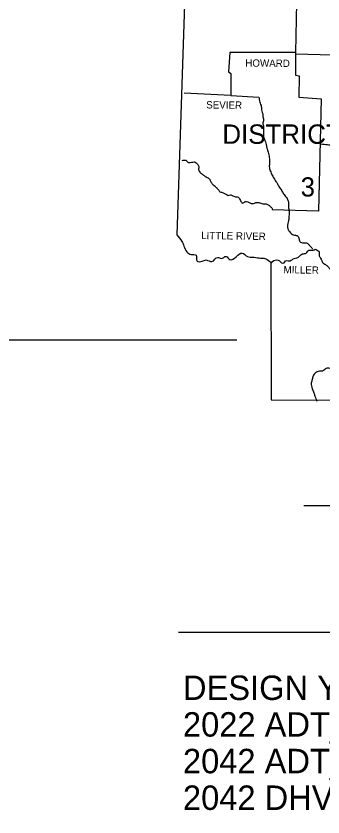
# Model space of a CAD drawing. Extents: x 1382482 to 1385815, y 1168351 to 1170484.
# Drawn here: x 1384992.8 to 1385181.4, y 1169422.5 to 1169914.2 of the extents above; entities that cross this region are included whole.
import ezdxf

# ---------------------------------------------------------------- set-up
doc = ezdxf.new("R2010")
doc.units = 0
for name, color, linetype in [('Default', 7, 'Continuous'), ('R_Dimension', 7, 'Continuous'), ('R_Draft', 7, 'Continuous')]:
    doc.layers.add(name, color=color, linetype=linetype)

msp = doc.modelspace()

# ---------------------------------------------------------------- linework, layer by layer
at = {"layer": 'Default'}
msp.add_line((1385169.72, 1169613.81), (1385528.6, 1169613.81), dxfattribs=at)
for points in [[(1385079.51, 1170236.59), (1385101.12, 1170063.06), (1385091.73, 1169779.8)], [(1385165.65, 1169943.09), (1385164.5, 1169891.73), (1385124.3, 1169891.83), (1385123.36, 1169879.93), (1385124.83, 1169878.88), (1385124.72, 1169865.52), (1385096.22, 1169866.77)], [(1385164.5, 1169891.73), (1385164.5, 1169877.84), (1385166.8, 1169877.42), (1385166.59, 1169864.47), (1385180.37, 1169863.43), (1385178.7, 1169794.42), (1385150.3, 1169795.15)], [(1385164.71, 1169890.99), (1385224.43, 1169889.43)], [(1385124.72, 1169865.52), (1385142.05, 1169864.47)], [(1385149.47, 1169762.99), (1385149.68, 1169678.52), (1385532.34, 1169677.9)]]:
    msp.add_lwpolyline(points, dxfattribs=at)
for points in [[(1385142.05, 1169864.47), (1385142.58, 1169861.34), (1385143.52, 1169858.63), (1385143.62, 1169856.54), (1385144.56, 1169853.41), (1385144.56, 1169852.26), (1385144.87, 1169849.96), (1385144.45, 1169848.71), (1385144.98, 1169846.2), (1385144.87, 1169844.32), (1385144.87, 1169842.76), (1385144.98, 1169840.15), (1385145.81, 1169837.85), (1385146.65, 1169834.4), (1385147.17, 1169832.63), (1385148, 1169829.92), (1385148.53, 1169826.57), (1385148.63, 1169824.07), (1385148.42, 1169821.77), (1385149.05, 1169819.16), (1385150.2, 1169816.55), (1385151.66, 1169814.04), (1385153.43, 1169811.23), (1385154.69, 1169809.03), (1385156.25, 1169806.63), (1385157.51, 1169804.65), (1385159.39, 1169802.14), (1385160.22, 1169800.05), (1385160.22, 1169797.13), (1385160.64, 1169794.42), (1385160.53, 1169791.39), (1385160.33, 1169788.67), (1385159.59, 1169784.91), (1385160.12, 1169783.14), (1385162.1, 1169780.53), (1385163.35, 1169779.8), (1385165.55, 1169779.38), (1385166.59, 1169777.92), (1385167.22, 1169775.73), (1385169.41, 1169775), (1385171.81, 1169774.79), (1385172.96, 1169773.53), (1385174.53, 1169771.86), (1385175.05, 1169771.03)], [(1385180.16, 1169835.66), (1385184.13, 1169835.34), (1385187.79, 1169834.93), (1385190.6, 1169834.61), (1385193.53, 1169833.57), (1385196.14, 1169832.63), (1385197.81, 1169831.9), (1385200.63, 1169832.11), (1385203.03, 1169831.59), (1385205.74, 1169830.65), (1385207.73, 1169828.87), (1385208.98, 1169827.51), (1385211.38, 1169826.99), (1385213.37, 1169827.3), (1385215.77, 1169827.1), (1385218.48, 1169826.26), (1385220.68, 1169826.37), (1385222.45, 1169826.78), (1385224.54, 1169827.3), (1385227.15, 1169827.51), (1385229.13, 1169827.1), (1385231.74, 1169826.99), (1385234.77, 1169827.3), (1385238.53, 1169826.26)], [(1385094.96, 1169825.53), (1385097.26, 1169825.63), (1385098.83, 1169824.28), (1385099.77, 1169824.38), (1385101.44, 1169824.59), (1385103, 1169824.49), (1385104.15, 1169823.55), (1385105.09, 1169821.88), (1385104.99, 1169820.31), (1385105.09, 1169819.68), (1385105.82, 1169818.33), (1385107.08, 1169817.28), (1385108.43, 1169816.24), (1385109.69, 1169815.4), (1385111.77, 1169814.04), (1385111.98, 1169813.63), (1385112.82, 1169811.96), (1385113.86, 1169810.6), (1385115.12, 1169809.76), (1385116.47, 1169808.3), (1385117.1, 1169807.68), (1385118.14, 1169806.21), (1385119.29, 1169806.11), (1385120.86, 1169805.17), (1385122.01, 1169804.86), (1385123.26, 1169804.02), (1385124.51, 1169804.44), (1385126.08, 1169803.81), (1385128.17, 1169803.19), (1385129.32, 1169802.98), (1385130.67, 1169800.99), (1385132.03, 1169799.32), (1385133.7, 1169800.26), (1385136.83, 1169799.32), (1385138.82, 1169799.22), (1385140.59, 1169799.74), (1385141.95, 1169799.64), (1385144.45, 1169799.01), (1385146.02, 1169799.01), (1385147.69, 1169798.38), (1385149.26, 1169797.13), (1385150.3, 1169795.77), (1385150.3, 1169795.15)], [(1385091.73, 1169779.8), (1385094.75, 1169775.83), (1385096.01, 1169773.01), (1385097.78, 1169769.36), (1385100.39, 1169767.9), (1385103.42, 1169767.37), (1385104.05, 1169763.82), (1385107.18, 1169763.72), (1385109.69, 1169764.45), (1385113.13, 1169763.51), (1385116.79, 1169766.02), (1385118.87, 1169765.39), (1385121.9, 1169766.64), (1385124.2, 1169764.76), (1385128.17, 1169766.43), (1385131.72, 1169768.73), (1385135.06, 1169766.54), (1385138.29, 1169766.23), (1385142.16, 1169765.7), (1385145.19, 1169765.49), (1385147.9, 1169764.14), (1385149.88, 1169762.78), (1385149.47, 1169762.99)], [(1385149.47, 1169762.99), (1385153.12, 1169764.55), (1385154.69, 1169764.03), (1385156.04, 1169762.68), (1385157.61, 1169762.68), (1385158.45, 1169763.93), (1385160.01, 1169764.03), (1385161.27, 1169763.93), (1385162.62, 1169764.76), (1385163.77, 1169765.29), (1385165.34, 1169765.81), (1385166.49, 1169766.23), (1385167.53, 1169767.37), (1385169.41, 1169768.31), (1385171.6, 1169769.04), (1385172.23, 1169770.09), (1385173.27, 1169770.51), (1385175.36, 1169770.4), (1385176.72, 1169771.03), (1385177.87, 1169770.51), (1385178.91, 1169769.78), (1385179.12, 1169767.06), (1385179.95, 1169765.6), (1385181.21, 1169762.99), (1385182.98, 1169761.63), (1385184.65, 1169760.27), (1385185.28, 1169759.44), (1385187.05, 1169757.87), (1385188.62, 1169757.35), (1385189.35, 1169756.2), (1385190.5, 1169753.49), (1385192.17, 1169751.09)], [(1385192.17, 1169751.09), (1385191.54, 1169748.06), (1385191.44, 1169745.66), (1385191.96, 1169742.84), (1385191.44, 1169741.48), (1385192.28, 1169739.5), (1385193.84, 1169737.93), (1385194.99, 1169736.26), (1385195.72, 1169733.86), (1385194.78, 1169731.14), (1385195.83, 1169728.32), (1385196.77, 1169727.28), (1385197.29, 1169725.61), (1385196.56, 1169722.37), (1385195.62, 1169719.97), (1385193.53, 1169717.57), (1385192.9, 1169716.42), (1385193.22, 1169714.86), (1385193.74, 1169712.35), (1385193.22, 1169711.62), (1385191.86, 1169709.84), (1385191.44, 1169707.86), (1385190.5, 1169706.19), (1385189.46, 1169703.16), (1385188.1, 1169700.66), (1385187.89, 1169697.84), (1385185.8, 1169697.84), (1385183.4, 1169697.84), (1385181.21, 1169696.27), (1385179.22, 1169696.17), (1385176.82, 1169695.23), (1385175.36, 1169693.24), (1385174.84, 1169691.05), (1385174.21, 1169688.96), (1385174.84, 1169685.41), (1385175.78, 1169682.91), (1385176.51, 1169680.92), (1385177.76, 1169677.69)]]:
    msp.add_spline(points, degree=3, dxfattribs=at)
at = {"layer": 'R_Dimension'}
msp.add_line((1384666.56, 1169715.52), (1385128.46, 1169715.53), dxfattribs=at)
at = {"layer": 'R_Draft'}
msp.add_line((1385092.56, 1169535.97), (1385557.75, 1169535.97), dxfattribs=at)

# ---------------------------------------------------------------- texts
at = {"layer": 'Default'}
for s, height, rotation, p in [('HOWARD', 4.49, 359.5145, (1385133.7, 1169883.16)), ('SEVIER', 4.49, 359.4271, (1385109.69, 1169857.48)), ('LITTLE RIVER', 4.4903, 359.1697, (1385106.55, 1169777.29)), ('MILLER', 4.489, 359.132, (1385157.19, 1169756.31))]:
    msp.add_text(s, height=height, rotation=rotation, dxfattribs=at).set_placement(p)
for s, height, p in [('DISTRICT', 11.903, (1385119.6, 1169835.76)), ('3', 11.8, (1385167.74, 1169803.4))]:
    msp.add_text(s, height=height, dxfattribs=at).set_placement(p)
at = {"layer": 'R_Draft'}
for s, p in [('DESIGN YEAR________________2042', (1385095.4, 1169494.36)), ('2022 ADT____________________750', (1385095.4, 1169471.86)), ('2042 ADT____________________830', (1385095.4, 1169449.36)), ('2042 DHV_____________________91', (1385095.4, 1169426.86))]:
    msp.add_text(s, height=15, dxfattribs=at).set_placement(p)

doc.saveas('drawing.dxf')
